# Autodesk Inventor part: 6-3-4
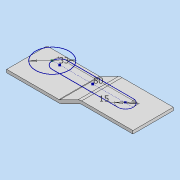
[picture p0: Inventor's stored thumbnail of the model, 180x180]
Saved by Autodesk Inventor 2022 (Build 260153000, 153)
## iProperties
Created: 2021-07
Part Number: 6-3-4
Material: 一般
Document SubType Name: Modeling
Designer: DesignLab
Density: 1 g/cm^3
Appearance: 既定
Author: DesignLab
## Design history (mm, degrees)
sketch "スケッチ1"
  geometry: L1 (25, 0)-(-28, 0); L2 (-28, 0)-(-48, 10); L3 (-48, 10)-(-100, 10); 1 further point
  constraints: 6 end point, 1 horizontal, 1 parallel, 1 point on line
  dimensions: "d0" = 25 distance of point (0, 0) L1.start; "d1" = 100 horizontal distance of L3.end point (0, 0); "d2" = 10 distance between parallel lines of L1 L3; "d3" = 28 distance of L1.end point (0, 0); "d4" = 20 horizontal distance of L1.end L2.end
feature "押し出しサーフェス1" sketch "スケッチ1" dims "d5" = 40, "d6" = 0
fillet "フィレット1" dims "d7" = 5
feature "厚み1" dims "d8" = 3
sketch "スケッチ2"
  geometry: L1 (-49.18, 20)-(30.82, 20); L2 (-41.68, 12.5)-(23.32, 12.5); L3 (23.32, 27.5)-(-41.68, 27.5); C1 r 16.5 at (-49.18, 20); A1 r 7.5 centre (-41.68, 20) between (-41.68, 27.5) and (-41.68, 12.5); A2 r 7.5 centre (23.32, 20) between (23.32, 12.5) and (23.32, 27.5); 2 further points
  constraints: 8 end point, 6 point on circle, 4 tangent, 3 centre point, 2 point on line, 1 coincident, 1 horizontal, 1 midpoint, 1 parallel
  dimensions: "d9" = 33 diameter of C1; "d10" = 80 distance of L1.start L1.end; "d11" = 15 diameter of A2
node "ソリッド1"
body "Srf1"
